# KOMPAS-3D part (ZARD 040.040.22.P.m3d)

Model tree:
1. Плоскость XY
2. Плоскость ZX
3. Плоскость ZY
4. Ось X
5. Ось Y
6. Ось Z
7. Начало координат
8. Булева операция:1
9. Булева операция:2
10. Булева операция:3
11. Булева операция:4
